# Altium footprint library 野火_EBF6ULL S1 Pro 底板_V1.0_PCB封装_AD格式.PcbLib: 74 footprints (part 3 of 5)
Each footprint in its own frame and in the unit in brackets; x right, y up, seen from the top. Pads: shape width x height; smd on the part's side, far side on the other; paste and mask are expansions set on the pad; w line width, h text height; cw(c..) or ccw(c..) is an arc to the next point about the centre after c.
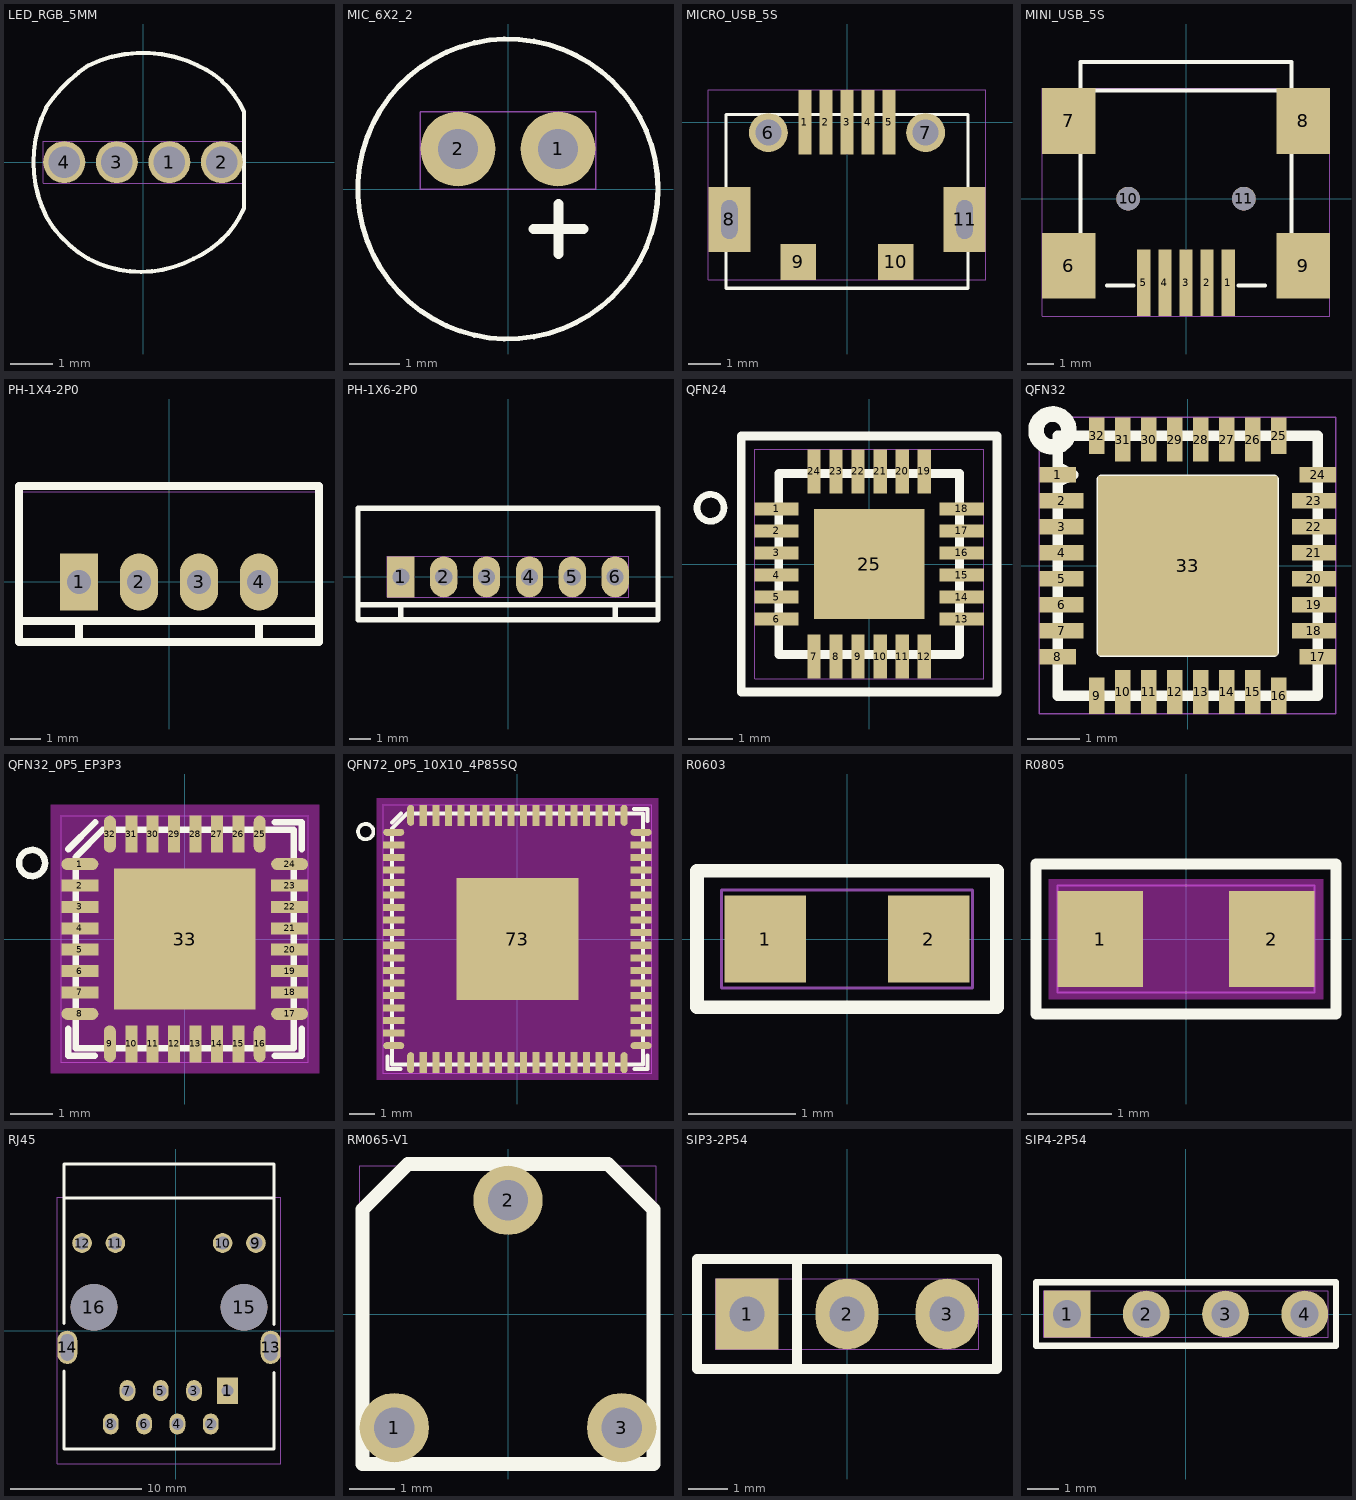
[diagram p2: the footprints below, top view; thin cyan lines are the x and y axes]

## LED_RGB_5MM [mm]
pads (4):
  round 1 hole 0.75 mask+0.05: 1(0.625,0) 2(1.875,0) 3(-0.625,0) 4(-1.875,0)
Top Overlay:
  lines w0.1: -2.301,1.297 ccw(c0.3,0) -2.299,-1.302 ; -2.299,-1.301 ccw(c0.05,0.05) -1.301,-2.299 ; -2.299,1.302 cw(c0.65,-0.65) -1.297,2.302 ; -1.3,-2.3 ccw(c-0.05,0.05) 1.2,-2.3 ; -1.299,2.301 cw(c0,-0.35) 1.303,2.298 ; 1.202,-2.299 ccw(c0.25,-0.15) 2.401,-1.098 ; 1.298,2.301 cw(c0.45,0.35) 2.399,1.202 ; 2.4,-1.1 2.4,1.2
Top Assembly:
  text "D11" at -1.182,-0.635 h1.27
Mechanical 20:
  lines w0.025: -2.375,-0.5 2.375,-0.5 2.375,0.5 -2.375,0.5 -2.375,-0.5

## MIC_6X2_2 [mil]
pads (2):
  round 59.06 hole 31.5 mask+2: 1(39.37,31.5) 2(-39.37,31.5)
Top Overlay:
  circle w4: c0,0 r118.11
  lines w7.87: 19.92,-31.61 59.29,-31.61 ; 39.61,-51.3 39.61,-11.93
Top Assembly:
  text "P1" at 28.21,25 h50
Mechanical 20:
  lines w1: -68.9,0 68.9,0 68.9,61.02 -68.9,61.02 -68.9,0

## MICRO_USB_5S [mm]
pads (11):
  rect 0.4x2 smd mask+0.05: 1(-1.3,0) 2(-0.65,0) 3(0,0) 4(0.65,0) 5(1.3,0)
  round 1.2 hole 0.8 mask+0.05: 6(-2.425,-0.32) 7(2.425,-0.32)
  rect 1.3x2 hole 0.5 slot 1.2 at 90 deg mask+0.05: 8(-3.625,-3) 11(3.625,-3)
  rect 1.1x1.1 smd mask+0.05: 9(-1.5,-4.31) 10(1.5,-4.31)
Top Overlay:
  lines w0.1: -3.73,-5.12 3.73,-5.12 ; -3.73,-5.12 -3.73,0.235 ; -3.73,-5.12 3.73,-5.12 ; -3.73,-5.12 -3.73,0.235 ; -3.73,0.235 3.73,0.235 ; -3.73,0.235 3.73,0.235 ; 3.73,-5.12 3.73,0.235 ; 3.73,-5.12 3.73,0.235
Top Assembly:
  text "J34" at -1.484,-0.635 h1.27
Mechanical 20:
  lines w0.025: -4.275,-4.86 4.275,-4.86 4.275,1 -4.275,1 -4.275,-4.86

## MINI_USB_5S [mil]
pads (11):
  rect 20x100 smd mask+2.5: 1(62.99,-125.98) 2(31.5,-125.98) 3(0,-125.98) 4(-31.5,-125.98) 5(-62.99,-125.98)
  rect 80x98.43 smd mask+2.5: 6(-175.2,-100.39) 7(-175.2,116.14) 8(175.2,116.14) 9(175.2,-100.39)
  round 35.43 hole 35.43 unplated mask+1.97: 10(-86.61,0) 11(86.61,0)
Top Overlay:
  lines w6: -157.48,-59.06 -157.48,74.8 ; -157.48,157.48 -157.48,204.72 157.48,204.72 157.48,157.48 ; -157.48,161.42 157.48,161.42 ; -118.11,-129.92 -78.74,-129.92 ; 78.74,-129.92 118.11,-129.92 ; 157.48,-59.06 157.48,74.8
Top Assembly:
  text "J9" at -33.81,-25 h50
Mechanical 20:
  lines w1: -215.2,-175.98 215.2,-175.98 215.2,165.35 -215.2,165.35 -215.2,-175.98

## PH-1X4-2P0 [mil]
pads (4):
  rect 50x75 hole 31.5 mask+2.5: 1(-118.11,0)
  oval 50x75 hole 31.5 mask+2.5: 2(-39.37,0) 3(39.37,0) 4(118.11,0)
Top Overlay:
  lines w10: -196.85,-51.18 196.85,-51.18 ; -118.11,-78.74 -118.11,-51.18 ; 118.11,-78.74 118.11,-51.18 ; -196.85,-78.74 -196.85,125.98 196.85,125.98 196.85,-78.74 -196.85,-78.74
Top Assembly:
  text "J33" at 57.25,25 h50
Mechanical 20:
  lines w1: -196.85,-78.74 -196.85,118.11 196.85,118.11 196.85,-78.74 -196.85,-78.74

## PH-1X6-2P0 [mil]
pads (6):
  rect 50x75 hole 31.5 mask+2.5: 1(-196.85,0)
  oval 50x75 hole 31.5 mask+2.5: 2(-118.11,0) 3(-39.37,0) 4(39.37,0) 5(118.11,0) 6(196.85,0)
Top Overlay:
  lines w10: -275.59,-51.18 275.59,-51.18 ; -196.85,-78.74 -196.85,-51.18 ; 196.85,-78.74 196.85,-51.18 ; -275.59,-78.74 275.59,-78.74 275.59,125.98 -275.59,125.98 -275.59,-78.74
Top Assembly:
  text "J39" at 56.06,25 h50
Mechanical 20:
  lines w1: -221.85,-37.5 221.85,-37.5 221.85,37.5 -221.85,37.5 -221.85,-37.5

## QFN24 [mm]
pads (25):
  rect 1x0.3 smd mask+0.05: 1(-2.1,1.25) 2(-2.1,0.75) 3(-2.1,0.25) 4(-2.1,-0.25) 5(-2.1,-0.75) 6(-2.1,-1.25) 13(2.1,-1.25) 14(2.1,-0.75) 15(2.1,-0.25) 16(2.1,0.25) 17(2.1,0.75) 18(2.1,1.25)
  rect 0.3x1 smd mask+0.05: 7(-1.25,-2.1) 8(-0.75,-2.1) 9(-0.25,-2.1) 10(0.25,-2.1) 11(0.75,-2.1) 12(1.25,-2.1) 19(1.25,2.1) 20(0.75,2.1) 21(0.25,2.1) 22(-0.25,2.1) 23(-0.75,2.1) 24(-1.25,2.1)
  rect 2.5x2.5 smd mask+0.05: 25(0,0)
Top Overlay:
  circle w0.152: c-3.599,1.275 r0.305
  lines w0.2: -2.9,-2.9 -2.9,2.9 2.9,2.9 2.9,-2.9 -2.9,-2.9 ; -2.05,-2.05 -2.05,2.05 2.05,2.05 2.05,-2.05 -2.05,-2.05
Top Assembly:
  text "U14" at 1.518,0.635 h1.27
Mechanical 20:
  lines w0.025: -2.6,-2.6 2.6,-2.6 2.6,2.6 -2.6,2.6 -2.6,-2.6

## QFN32 [mil]
pads (33):
  rect 27.56x11.81 smd mask+1.97: 1(-98.43,68.9) 8(-98.43,-68.9) 17(98.43,-68.9) 24(98.43,68.9)
  rect 33.46x11.81 smd mask+1.97: 2(-95.47,49.21) 3(-95.47,29.53) 4(-95.47,9.84) 5(-95.47,-9.84) 6(-95.47,-29.53) 7(-95.47,-49.21) 18(95.47,-49.21) 19(95.47,-29.53) 20(95.47,-9.84) 21(95.47,9.84) 22(95.47,29.53) 23(95.47,49.21)
  rect 11.81x27.56 smd mask+1.97: 9(-68.9,-98.43) 16(68.9,-98.43) 25(68.9,98.43) 32(-68.9,98.43)
  rect 11.81x33.46 smd mask+1.97: 10(-49.21,-95.47) 11(-29.53,-95.47) 12(-9.84,-95.47) 13(9.84,-95.47) 14(29.53,-95.47) 15(49.21,-95.47) 26(49.21,95.47) 27(29.53,95.47) 28(9.84,95.47) 29(-9.84,95.47) 30(-29.53,95.47) 31(-49.21,95.47)
  rect 135.83x135.83 smd mask+1.97: 33(0,0)
Top Overlay:
  circle w11.81: c-102.36,102.36 r12.45
  lines w7.87: -98.43,-98.43 -98.43,62.99 -86.61,68.9 -98.43,74.8 -98.43,98.43 98.43,98.43 98.43,-98.43 -98.43,-98.43 ; -64.96,-64.96 -64.96,64.96 64.96,64.96 64.96,-64.96 -64.96,-64.96
Top Assembly:
  text "U16" at -57.37,-25 h50
Mechanical 20:
  lines w1: -112.2,-112.2 112.2,-112.2 112.2,112.2 -112.2,112.2 -112.2,-112.2

## QFN32_0P5_EP3P3 [mil]
height 39
pads (33):
  oval 34x11 smd mask+2: 1(-96.46,68.9) 8(-96.46,-68.9) 17(96.46,-68.9) 24(96.46,68.9)
  rect 34x11 smd mask+2: 2(-96.46,49.21) 3(-96.46,29.53) 4(-96.46,9.84) 5(-96.46,-9.84) 6(-96.46,-29.53) 7(-96.46,-49.21) 18(96.46,-49.21) 19(96.46,-29.53) 20(96.46,-9.84) 21(96.46,9.84) 22(96.46,29.53) 23(96.46,49.21)
  oval 11x34 smd mask+2: 9(-68.9,-96.46) 16(68.9,-96.46) 25(68.9,96.46) 32(-68.9,96.46)
  rect 11x34 smd mask+2: 10(-49.21,-96.46) 11(-29.53,-96.46) 12(-9.84,-96.46) 13(9.84,-96.46) 14(29.53,-96.46) 15(49.21,-96.46) 26(49.21,96.46) 27(29.53,96.46) 28(9.84,96.46) 29(-9.84,96.46) 30(-29.53,96.46) 31(-49.21,96.46)
  rect 130x130 smd mask+2: 33(0,0)
Top Layer keep-out:
  region: -123.46,-123.46 -123.46,123.46 123.46,123.46 123.46,-123.46
Top Overlay:
  circle w5.98: c-140.48,69.89 r12.02
  lines w6: -107.39,-82.68 -107.39,-107.39 -82.68,-107.39 ; -107.39,82.39 -82.39,107.39 ; 82.68,-107.39 107.39,-107.39 107.39,-82.68 ; 82.68,107.39 107.39,107.39 107.39,82.68 ; -100.39,-100.39 -100.39,75.39 -75.39,100.39 100.39,100.39 100.39,-100.39 -100.39,-100.39
Top Paste:
  lines w1: -59.06,-59.06 -59.06,-5.91 -5.91,-5.91 -5.91,-59.06 -59.06,-59.06 ; -59.06,5.91 -5.91,5.91 -5.91,59.06 -59.06,59.06 -59.06,5.91 ; 5.91,-59.06 59.06,-59.06 59.06,-5.91 5.91,-5.91 5.91,-59.06 ; 5.91,5.91 59.06,5.91 59.06,59.06 5.91,59.06 5.91,5.91
Top Assembly:
  text "U13" at 58.56,25 h50
Mechanical 20:
  lines w1: -113.46,-113.46 113.46,-113.46 113.46,113.46 -113.46,113.46 -113.46,-113.46

## QFN72_0P5_10X10_4P85SQ [mil]
height 35
pads (73):
  oval 33x11 smd mask+2: 1(-193.9,167.32) 18(-193.9,-167.24) 37(193.9,-167.24) 54(193.9,167.32)
  rect 33x11 smd mask+2: 2(-193.9,147.64) 3(-193.9,127.96) 4(-193.9,108.28) 5(-193.9,88.6) 6(-193.9,68.92) 7(-193.9,49.24) 8(-193.9,29.56) 9(-193.9,9.88) 10(-193.9,-9.8) 11(-193.9,-29.48) 12(-193.9,-49.16) 13(-193.9,-68.84) 14(-193.9,-88.52) 15(-193.9,-108.2) 16(-193.9,-127.88) 17(-193.9,-147.56) 38(193.9,-147.56) 39(193.9,-127.88) 40(193.9,-108.2) 41(193.9,-88.52) 42(193.9,-68.84) 43(193.9,-49.16) 44(193.9,-29.48) 45(193.9,-9.8) 46(193.9,9.88) 47(193.9,29.56) 48(193.9,49.24) 49(193.9,68.92) 50(193.9,88.6) 51(193.9,108.28) 52(193.9,127.96) 53(193.9,147.64)
  oval 11x33 smd mask+2: 19(-167.32,-193.9) 36(167.24,-193.9) 55(167.24,193.9) 72(-167.32,193.9)
  rect 11x33 smd mask+2: 20(-147.64,-193.9) 21(-127.96,-193.9) 22(-108.28,-193.9) 23(-88.6,-193.9) 24(-68.92,-193.9) 25(-49.24,-193.9) 26(-29.56,-193.9) 27(-9.88,-193.9) 28(9.8,-193.9) 29(29.48,-193.9) 30(49.16,-193.9) 31(68.84,-193.9) 32(88.52,-193.9) 33(108.2,-193.9) 34(127.88,-193.9) 35(147.56,-193.9) 56(147.56,193.9) 57(127.88,193.9) 58(108.2,193.9) 59(88.52,193.9) 60(68.84,193.9) 61(49.16,193.9) 62(29.48,193.9) 63(9.8,193.9) 64(-9.88,193.9) 65(-29.56,193.9) 66(-49.24,193.9) 67(-68.92,193.9) 68(-88.6,193.9) 69(-108.28,193.9) 70(-127.96,193.9) 71(-147.64,193.9)
  rect 191x191 smd mask+2: 73(0,0)
Top Layer keep-out:
  region: -220.4,-220.4 -220.4,220.4 220.4,220.4 220.4,-220.4
Top Overlay:
  circle w5.98: c-237.92,168.31 r12.02
  lines w6: -203.85,-183.74 -203.85,-203.85 -183.18,-203.85 ; -196.83,182.67 -182.65,196.85 ; 182.99,203.85 203.85,203.85 203.85,184.94 ; 183.79,-203.85 203.85,-203.85 203.85,-182.75 ; -196.85,-196.85 -196.85,173.23 -173.23,196.85 196.85,196.85 196.85,-196.85 -196.85,-196.85
Top Paste:
  lines w1: -81.52,-81.52 -13.98,-81.52 -13.98,-13.98 -81.52,-13.98 -81.52,-81.52 ; -81.52,13.98 -13.98,13.98 -13.98,81.52 -81.52,81.52 -81.52,13.98 ; 13.98,-81.52 81.52,-81.52 81.52,-13.98 13.98,-13.98 13.98,-81.52 ; 13.98,13.98 81.52,13.98 81.52,81.52 13.98,81.52 13.98,13.98
Top Assembly:
  text "U20" at 62.49,25 h50
Mechanical 20:
  lines w1: -210.4,-210.4 -210.4,210.4 210.4,210.4 210.4,-210.4 -210.4,-210.4

## R0603 [mil]
pads (2):
  rect 30x32 smd mask+2.5: 1(-30,0) 2(30,0)
Top Overlay:
  lines w5: -55,-25 -55,25 55,25 55,-25 -55,-25
Top Assembly:
  text "R99" at 59.99,25 h50
Mechanical 20:
  lines w1: -46,-18 -46,18 46,18 46,-18 -46,-18

## R0805 [mil]
pads (2):
  rect 40x45 smd mask+4: 1(-40,0) 2(40,0)
Top Layer keep-out:
  region: -64,-28 -64,28 64,28 64,-28
Top Overlay:
  lines w5: -70,-35 -70,35 70,35 70,-35 -70,-35
Top Assembly:
  text "R216" at -78.32,-25 h50
Mechanical 20:
  lines w1: -60,-25 -60,25 60,25 60,-25 -60,-25

## RJ45 [mil]
pads (16):
  rect 62.99x78.74 / inner oval 62.99x78.74 / far side rect 62.99x78.74 hole 35.43 mask+1.97: 1(155.2,-180)
  oval 47.24x62.99 hole 35.43 mask+1.97: 2(105.2,-280) 3(55.2,-180) 4(5.2,-280) 5(-44.8,-180) 6(-94.8,-280) 7(-144.8,-180) 8(-194.8,-280)
  round 59.06 hole 40.16 mask+2.5: 9(240.83,262.91) 10(140.83,262.91) 11(-180.83,262.91) 12(-280.83,262.91)
  oval 60x100 hole 40 slot 80 at 90 deg mask+2.5: 13(285.12,-50.08) 14(-325.12,-50.08)
  round 140 hole 140 unplated mask+2.5: 15(205,70) 16(-245,70)
Top Overlay:
  lines w7.87: -334.96,397.76 294.96,397.76
  lines w10: -334.96,-120.83 -334.96,-355 294.96,-355 294.96,-125.98 ; -334.96,22.64 -334.96,499.92 294.96,499.92 294.96,18.94
Top Assembly:
  text "J25" at -57.25,-25 h50
Mechanical 20:
  lines w1: -355.12,-400 -355.12,400 315.12,400 315.12,-400 -355.12,-400

## RM065-V1 [mil]
pads (3):
  round 60 hole 35 mask+2.5: 1(-98.43,-98.43) 2(0,98.43) 3(98.43,-98.43)
Top Overlay:
  lines w12: -125.98,-129.92 125.98,-129.92 125.98,90.55 86.61,129.92 -86.61,129.92 -125.98,90.55 -125.98,-129.92
Top Assembly:
  text "RA1" at -53.09,-25 h50
Mechanical 20:
  lines w1: -128.43,-128.43 128.43,-128.43 128.43,128.43 -128.43,128.43 -128.43,-128.43

## SIP3-2P54 [mil]
pads (3):
  rect 62.99x70.87 hole 35.43 mask+1.97: 1(-100,0)
  oval 62.99x70.87 hole 35.43 mask+1.97: 2(0,0) 3(100,0)
Top Overlay:
  lines w10: -50,-55.12 -50,55.12 ; -150,-55.12 -150,55.12 150,55.12 150,-55.12 -150,-55.12
Top Assembly:
  text "J29" at -56.06,-25 h50
Mechanical 20:
  lines w1: -131.5,-35.43 131.5,-35.43 131.5,35.43 -131.5,35.43 -131.5,-35.43

## SIP4-2P54 [mil]
pads (4):
  rect 59.06x59.06 / inner round 59.06 / far side rect 59.06x59.06 hole 35.43 mask+1.97: 1(-150,0)
  round 59.06 hole 35.43 mask+1.97: 2(-50,0) 3(50,0) 4(150,0)
Top Overlay:
  lines w7.87: -189.37,-40 189.57,-40 189.57,40 -189.37,40 -189.37,-40
Top Assembly:
  text "J27" at -57.25,-25 h50
Mechanical 20:
  lines w1: -179.53,-29.53 179.53,-29.53 179.53,29.53 -179.53,29.53 -179.53,-29.53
